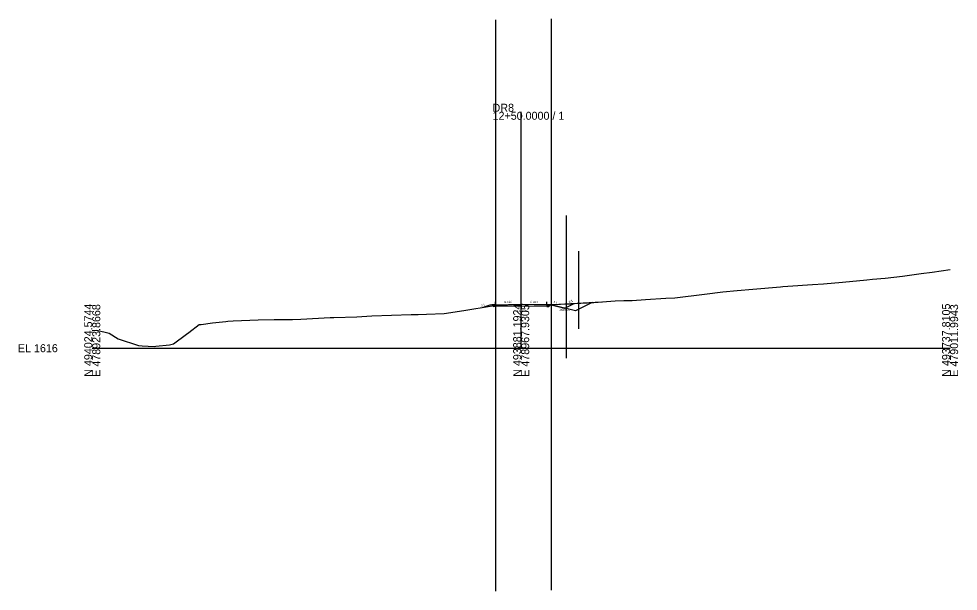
# Model space of a CAD drawing. Extents: x 24 to 353, y -10 to 3552.
# Drawn here: x 24.3 to 352.8, y 2414.9 to 2615.3 of the extents above; entities that cross this region are included whole.
import ezdxf

# ---------------------------------------------------------------- set-up
doc = ezdxf.new("R2010")
doc.units = 0
for name, color, linetype in [('Exist Cross Section Cell', 7, 'Continuous'), ('Exist XS Center Line Elevation Label', 7, 'Continuous'), ('Exist XS Ground Line', 7, 'Continuous'), ('Prop XS Ditch Slope Text', 7, 'Continuous'), ('Prop XS Ditch Standard Text', 7, 'Continuous'), ('Prop XS Dump Level', 7, 'Continuous'), ('Prop XS Earthwork Shape', 7, 'Continuous'), ('Prop XS EOT Tick Mark', 7, 'Continuous'), ('Prop XS Finish Grade', 7, 'Continuous'), ('Prop XS Finish Grade Earthwork', 7, 'Continuous'), ('Prop XS Finish Grade Pavement', 7, 'Continuous'), ('Prop XS Hydro Typical Ditch Data', 7, 'Continuous'), ('Prop XS Pvmt Edge Slope', 7, 'Continuous'), ('Prop XS SE Text', 7, 'Continuous'), ('Prop XS Shoulder Borrow Shape', 7, 'Continuous'), ('Prop XS Side Slope Text', 7, 'Continuous'), ('Prop XS Subgrade Earthwork', 7, 'Continuous'), ('Scratch_Level_1', 7, 'Continuous'), ('Scratch_Level_2', 7, 'Continuous'), ('Scratch_Level_4', 7, 'Continuous'), ('Scratch_Level_5', 7, 'Continuous')]:
    doc.layers.add(name, color=color, linetype=linetype)

msp = doc.modelspace()

# ---------------------------------------------------------------- linework, layer by layer
at = {"layer": 'Exist Cross Section Cell'}
for p, q in [((200, 2500), (200, 2582.75)), ((50, 2500), (200, 2500)), ((200, 2500), (350, 2500))]:
    msp.add_line(p, q, dxfattribs=at)
at = {"layer": 'Exist XS Ground Line'}
msp.add_lwpolyline([(50, 2506.24), (51.63, 2506.31), (55.92, 2505.25), (59.03, 2503.23), (66.19, 2500.92), (67.4, 2500.87), (71.63, 2500.63), (72.24, 2500.72), (77.03, 2501.14), (78.46, 2501.55), (82.99, 2504.96), (83.72, 2505.49), (87.39, 2508.25), (88.1, 2508.28), (92.03, 2508.85), (96.67, 2509.38), (97.4, 2509.44), (99.27, 2509.55), (108.01, 2509.87), (113.62, 2510.02), (117.76, 2510.03), (120.08, 2510.1), (122.9, 2510.15), (133.21, 2510.69), (134.45, 2510.72), (142.47, 2510.98), (147.81, 2511.27), (161.58, 2511.79), (164.02, 2511.84), (166.86, 2511.95), (173.02, 2512.14), (180, 2513.19), (189.85, 2514.88), (196.99, 2515.26), (200, 2515.41), (200.49, 2515.43), (209.02, 2515.31), (210.86, 2515.29), (216.84, 2515.54), (217.7, 2515.57), (218.16, 2515.6), (218.66, 2515.62), (225.41, 2516.02), (232.86, 2516.53), (235.9, 2516.7), (238.79, 2516.75), (243.46, 2516.99), (250.59, 2517.55), (253.73, 2517.67), (264.16, 2518.94), (270.53, 2519.73), (275.55, 2520.14), (280.99, 2520.63), (290.65, 2521.46), (291.46, 2521.54), (293.26, 2521.66), (301.92, 2522.24), (305.76, 2522.53), (312.38, 2523.08), (320.87, 2523.92), (322.85, 2524.11), (327.31, 2524.56), (333.31, 2525.17), (339.9, 2526.09), (343.77, 2526.64), (350, 2527.58)], dxfattribs=at)
at = {"layer": 'Prop XS Dump Level'}
for p, q in [((191, 2515.22), (200, 2515.4)), ((200, 2515.4), (209, 2515.22))]:
    msp.add_line(p, q, dxfattribs=at)
at = {"layer": 'Prop XS Earthwork Shape'}
for points in [[(189.74, 2515.12), (189, 2515.06), (186.98, 2514.39), (189.85, 2514.88), (189.97, 2514.89)], [(209, 2514.56), (200, 2514.74), (191, 2514.56), (190.32, 2514.54), (189.97, 2514.89), (196.99, 2515.26), (200, 2515.41), (200.49, 2515.43), (209.02, 2515.31), (210.86, 2515.29), (216.84, 2515.54), (217.7, 2515.57), (218.16, 2515.6), (218.66, 2515.62), (224.85, 2515.99), (219, 2513.06), (211, 2515.06), (210.26, 2515.12), (209.68, 2514.54)]]:
    msp.add_lwpolyline(points, close=True, dxfattribs=at)
at = {"layer": 'Prop XS EOT Tick Mark'}
for p, q in [((191, 2515.22), (191, 2516.22)), ((209, 2515.22), (209, 2516.22))]:
    msp.add_line(p, q, dxfattribs=at)
at = {"layer": 'Prop XS Finish Grade'}
for p, q in [((191, 2515.22), (189.74, 2515.12)), ((209, 2515.22), (210.26, 2515.12))]:
    msp.add_line(p, q, dxfattribs=at)
at = {"layer": 'Prop XS Finish Grade Earthwork'}
for p, q in [((189, 2515.06), (186.98, 2514.39)), ((189.74, 2515.12), (189, 2515.06)), ((210.26, 2515.12), (211, 2515.06)), ((211, 2515.06), (215.26, 2514)), ((215.26, 2514), (218.48, 2515.61))]:
    msp.add_line(p, q, dxfattribs=at)
at = {"layer": 'Prop XS Finish Grade Pavement'}
for p, q in [((191, 2515.22), (200, 2515.4)), ((200, 2515.4), (209, 2515.22))]:
    msp.add_line(p, q, dxfattribs=at)
at = {"layer": 'Prop XS Hydro Typical Ditch Data'}
for p, q in [((211, 2515.06), (215.26, 2514)), ((215.26, 2514), (218.48, 2515.61))]:
    msp.add_line(p, q, dxfattribs=at)
at = {"layer": 'Prop XS Pvmt Edge Slope'}
for p, q in [((191, 2515.22), (190.32, 2514.54)), ((209, 2515.22), (209.68, 2514.54))]:
    msp.add_line(p, q, dxfattribs=at)
at = {"layer": 'Prop XS Shoulder Borrow Shape'}
for points in [[(191, 2515.22), (189.74, 2515.12), (190.32, 2514.54)], [(191, 2515.22), (189.74, 2515.12), (190.32, 2514.54)], [(191, 2515.22), (189.74, 2515.12), (190.32, 2514.54)], [(209, 2515.22), (210.26, 2515.12), (209.68, 2514.54)], [(209, 2515.22), (210.26, 2515.12), (209.68, 2514.54)], [(209, 2515.22), (210.26, 2515.12), (209.68, 2514.54)]]:
    msp.add_lwpolyline(points, close=True, dxfattribs=at)
at = {"layer": 'Prop XS Subgrade Earthwork'}
for p, q in [((190.32, 2514.54), (189.74, 2515.12)), ((191, 2514.56), (190.32, 2514.54)), ((200, 2514.74), (191, 2514.56)), ((209, 2514.56), (200, 2514.74)), ((209, 2514.56), (209.68, 2514.54)), ((209.68, 2514.54), (210.26, 2515.12))]:
    msp.add_line(p, q, dxfattribs=at)
at = {"layer": 'Scratch_Level_1'}
msp.add_line((220, 2534), (220, 2506.81), dxfattribs=at)
at = {"layer": 'Scratch_Level_2'}
for p, q in [((210.44, 2615.3), (210.44, 2415.3)), ((210.44, 2615.3), (210.44, 2415.3)), ((191, 2614.94), (191, 2414.94)), ((191, 2614.94), (191, 2414.94))]:
    msp.add_line(p, q, dxfattribs=at)
at = {"layer": 'Scratch_Level_4'}
msp.add_line((209, 2515.22), (228, 2516.2), dxfattribs=at)
at = {"layer": 'Scratch_Level_5'}
for p, q in [((215.77, 2546.49), (215.77, 2496.49)), ((191, 2545.94), (191, 2495.94))]:
    msp.add_line(p, q, dxfattribs=at)
msp.add_lwpolyline([(50, 2506.24), (51.63, 2506.31), (55.92, 2505.25), (59.03, 2503.23), (66.19, 2500.92), (67.4, 2500.87), (71.63, 2500.63), (72.24, 2500.72), (77.03, 2501.14), (78.46, 2501.55), (82.99, 2504.96), (83.72, 2505.49), (87.39, 2508.25), (88.1, 2508.28), (92.03, 2508.85), (96.67, 2509.38), (97.4, 2509.44), (99.27, 2509.55), (108.01, 2509.87), (113.62, 2510.02), (117.76, 2510.03), (120.08, 2510.1), (122.9, 2510.15), (133.21, 2510.69), (134.45, 2510.72), (142.47, 2510.98), (147.81, 2511.27), (161.58, 2511.79), (164.02, 2511.84), (166.86, 2511.95), (173.02, 2512.14), (180, 2513.19), (189.85, 2514.88), (196.99, 2515.26), (200, 2515.41), (200.49, 2515.43), (209.02, 2515.31), (210.86, 2515.29), (216.84, 2515.54), (217.7, 2515.57), (218.16, 2515.6), (218.66, 2515.62), (225.41, 2516.02), (232.86, 2516.53), (235.9, 2516.7), (238.79, 2516.75), (243.46, 2516.99), (250.59, 2517.55), (253.73, 2517.67), (264.16, 2518.94), (270.53, 2519.73), (275.55, 2520.14), (280.99, 2520.63), (290.65, 2521.46), (291.46, 2521.54), (293.26, 2521.66), (301.92, 2522.24), (305.76, 2522.53), (312.38, 2523.08), (320.87, 2523.92), (322.85, 2524.11), (327.31, 2524.56), (333.31, 2525.17), (339.9, 2526.09), (343.77, 2526.64), (350, 2527.58)], dxfattribs=at)

# ---------------------------------------------------------------- texts
at = {"layer": 'Exist Cross Section Cell'}
for s, p in [('DR8', (190, 2582.75)), ('12+50.0000 / 1', (190, 2579.95)), ('EL 1616', (24, 2498.6))]:
    msp.add_text(s, height=2.8, dxfattribs=at).set_placement(p)
for s, p in [('N 494024.5744', (50, 2490)), ('E 478923.8668', (52.8, 2490)), ('N 493881.1924', (200, 2490)), ('E 478967.9305', (202.8, 2490)), ('N 493737.8105', (350, 2490)), ('E 479011.9943', (352.8, 2490))]:
    msp.add_text(s, height=2.8, rotation=90, dxfattribs=at).set_placement(p)
at = {"layer": 'Exist XS Center Line Elevation Label'}
msp.add_text('1631.41', height=0.75, dxfattribs=at).set_placement((198.56, 2512.66))
at = {"layer": 'Prop XS Ditch Slope Text'}
msp.add_text('4:1', height=0.75, rotation=345.9638, dxfattribs=at).set_placement((211.23, 2515.87))
at = {"layer": 'Prop XS Ditch Standard Text'}
msp.add_text('1630.00', height=0.75, dxfattribs=at).set_placement((213.31, 2513.13))
at = {"layer": 'Prop XS Dump Level'}
for p in [(189, 2515.02), (211, 2515.02)]:
    msp.add_text('Case1', height=0.04, dxfattribs=at).set_placement(p)
at = {"layer": 'Prop XS SE Text'}
for rotation, p in [(1.1458, (194.18, 2515.79)), (358.8542, (203.18, 2515.84))]:
    msp.add_text('0.020', height=0.75, rotation=rotation, dxfattribs=at).set_placement(p)
at = {"layer": 'Prop XS Side Slope Text'}
for s, rotation, p in [('2:1', 26.5651, (216.86, 2515.74)), ('3:1', 21.6107, (186.08, 2514.45))]:
    msp.add_text(s, height=0.75, rotation=rotation, dxfattribs=at).set_placement(p)

doc.saveas('drawing.dxf')
